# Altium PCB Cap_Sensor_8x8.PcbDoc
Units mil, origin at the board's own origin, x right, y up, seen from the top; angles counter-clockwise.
Board outline 3170 x 4550 mil, 2 copper layers (Top Layer, Bottom Layer); 74 components, 83 nets, 392 pads, 146 vias.
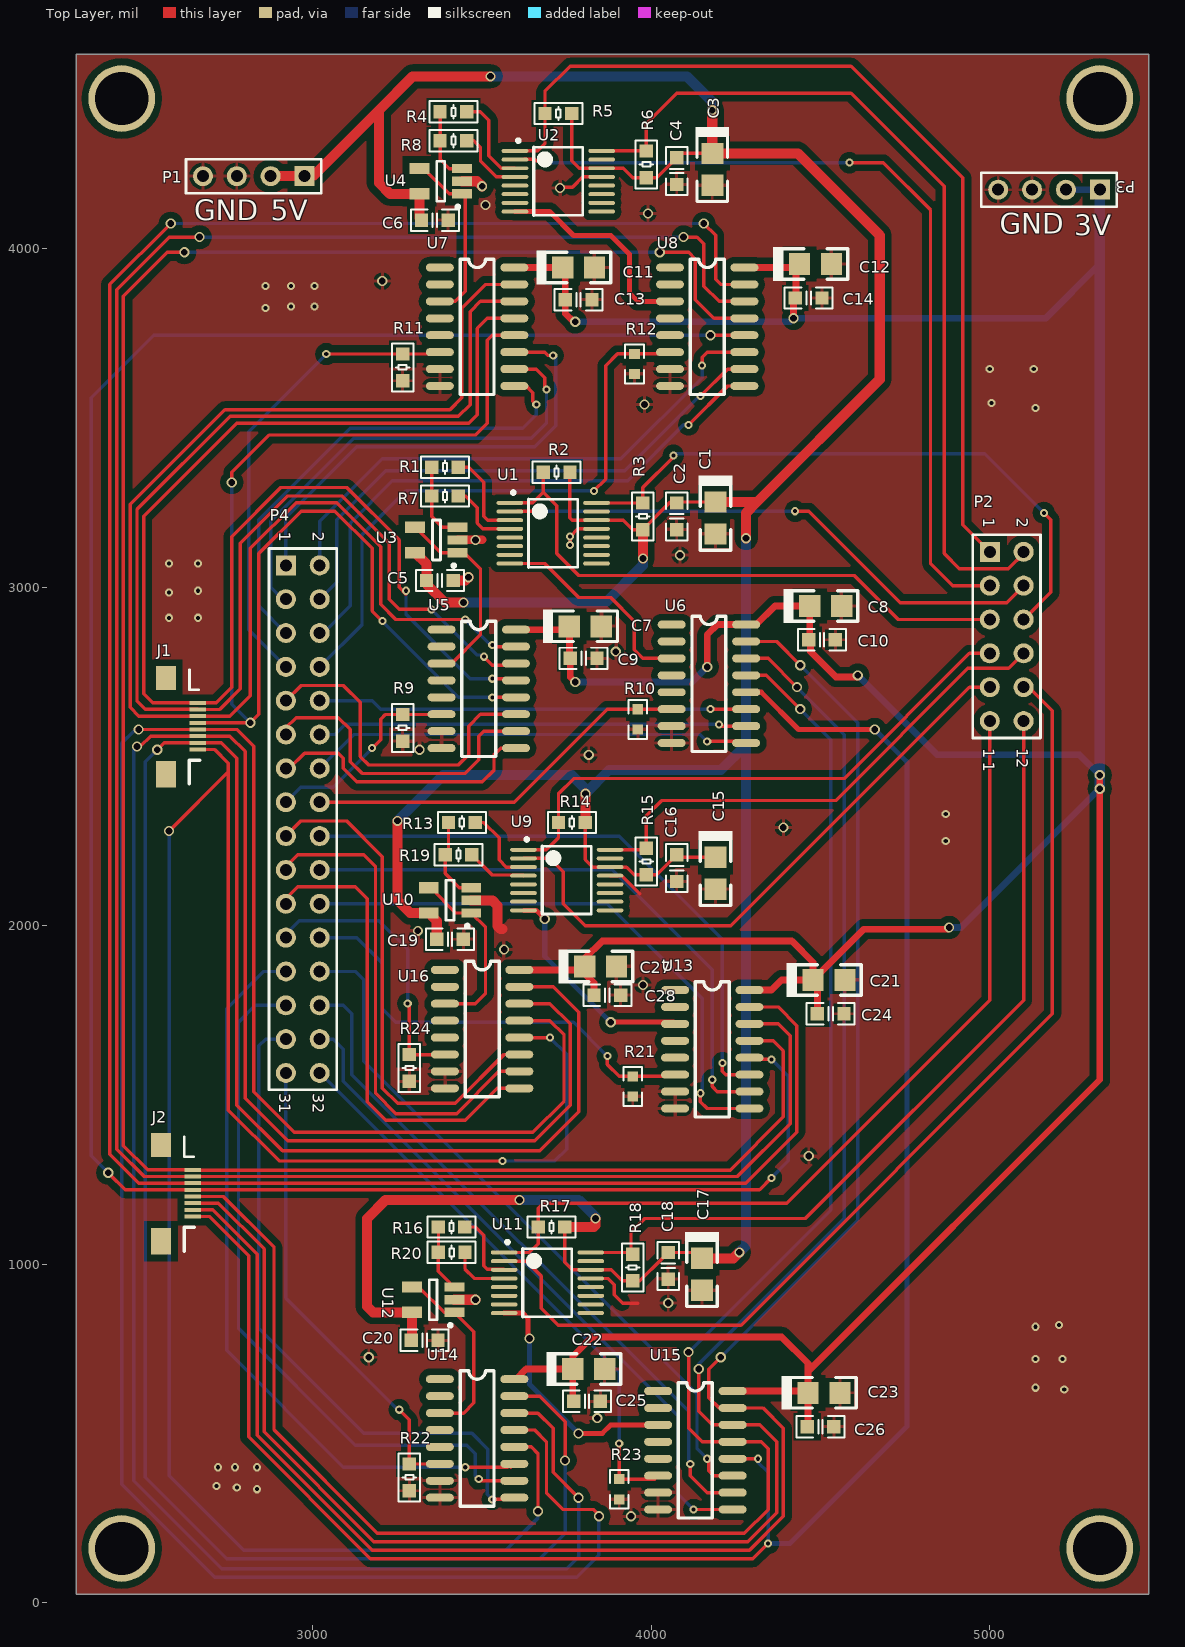
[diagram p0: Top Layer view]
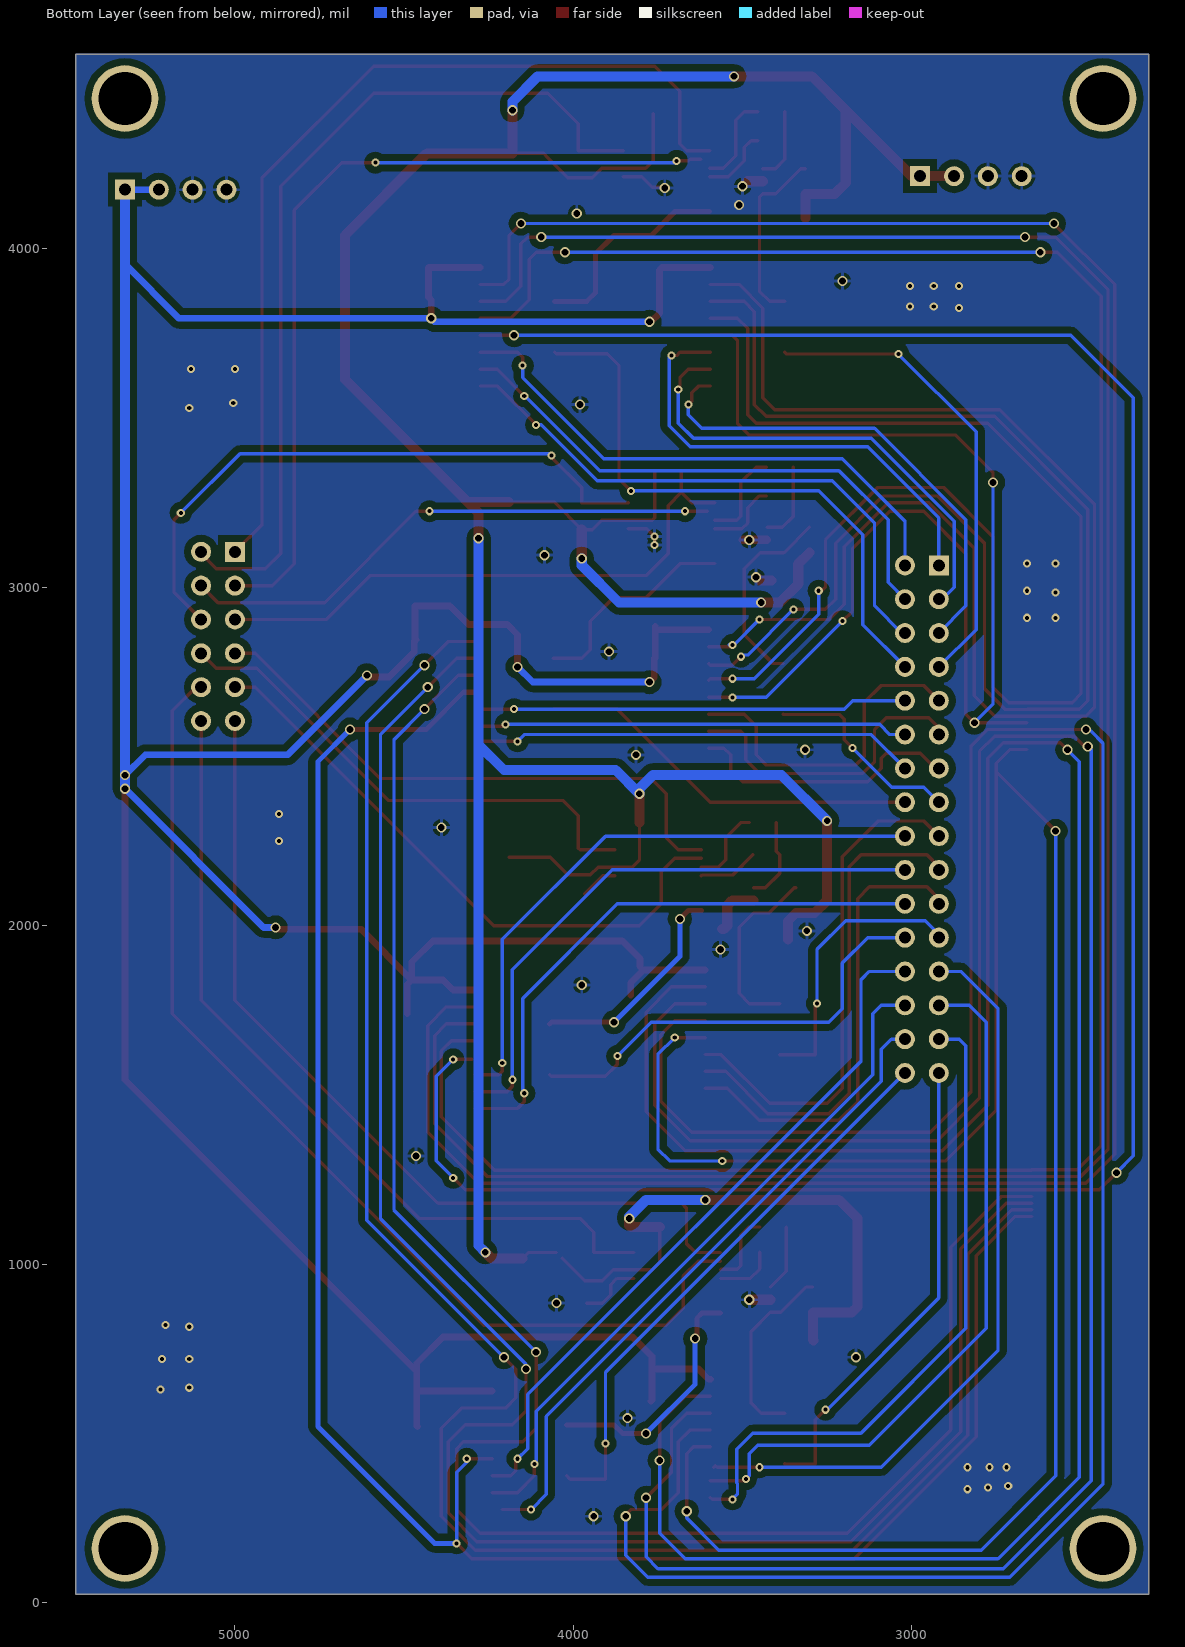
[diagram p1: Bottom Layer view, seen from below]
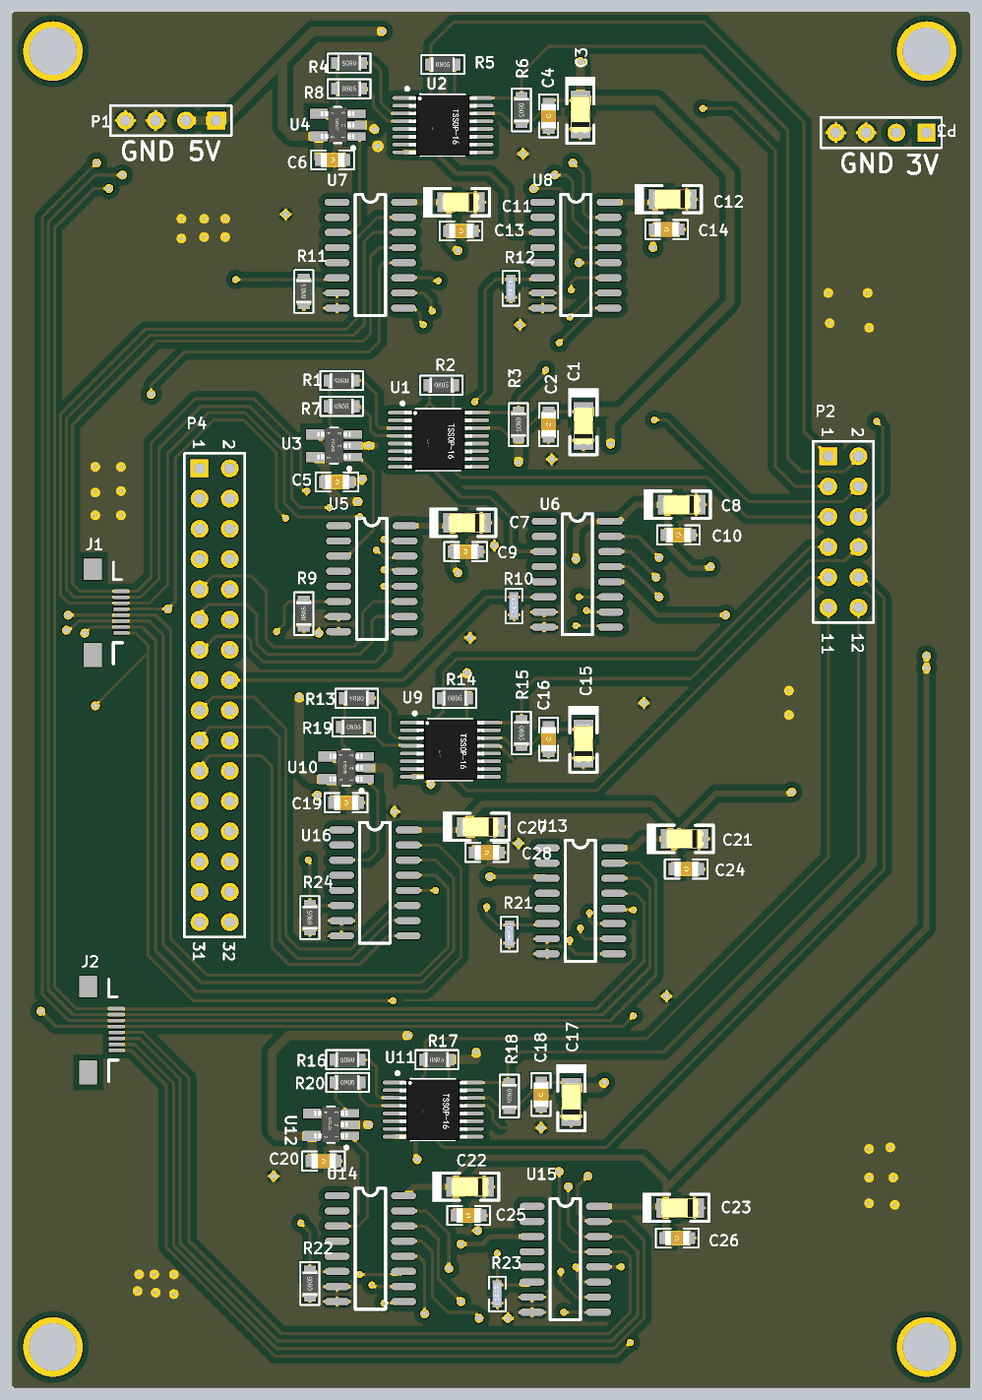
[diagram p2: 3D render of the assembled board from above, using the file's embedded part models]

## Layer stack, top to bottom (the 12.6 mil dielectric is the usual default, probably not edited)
Top Solder: solder mask 0.4, Solder Resist, Dk 3.5
Top Layer: signal copper 1.4
Dielectric 1: dielectric 12.6, FR-4, Dk 4.8
Bottom Layer: signal copper 1.4
Bottom Solder: solder mask 0.4, Solder Resist, Dk 3.5

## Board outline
2300,25 2300,4575 5470,4575 5470,25

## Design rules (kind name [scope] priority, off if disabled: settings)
Clearance Clearance_1 [InPolygon] p1: gap=20 ignorepadtopadclearanceinfootprint=FALSE except(0: Arc-Hole Track-Hole SMDPad-Hole THPad-Hole Via-Hole Fill-Hole Poly-Hole Region-Hole Text-Hole)
Clearance [All] p2: gap=4 ignorepadtopadclearanceinfootprint=FALSE except(0: Arc-Hole Track-Hole SMDPad-Hole THPad-Hole Via-Hole Fill-Hole Poly-Hole Region-Hole Text-Hole)
PolygonConnect [All] p1: connectstyle=Relief reliefconductorwidth=10 reliefentries=4 polygonreliefangle="90 Angle" airgapwidth=10
RoutingVias [All] p1: holewidth=20 width=30 viastyle="Through Hole" minholewidth=20 minwidth=30 maxholewidth=20 maxwidth=30
SolderMaskExpansion [All] p1: expansion=4
Width Width_1 [All] p1: maxlimit=30 minlimit=10 preferedwidth=20
Width Width_vcc [InNet('VDD_5V')] p2: maxlimit=50 minlimit=10 preferedwidth=20
30 further rules are at their usual default settings.

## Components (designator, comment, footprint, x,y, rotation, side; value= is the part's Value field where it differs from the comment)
C1 "Cap Pol2" Cap-TA 4190,3205 r90 top
C2 "Cap" 0805C 4075,3210 r90 top
C3 "Cap Pol2" Cap-TA 4180,4235 r90 top
C4 "Cap" 0805C 4075,4230 r90 top
C5 "Cap" 0805C 3375,3020 r180 top
C6 "Cap" 0805C 3360,4085 r180 top
C7 "Cap Pol2" Cap-TA 3805,2885 r180 top
C8 "Cap Pol2" Cap-TA 4515,2945 r180 top
C9 "Cap" 0805C 3800,2790 r180 top
C10 "Cap" 0805C 4504.37,2845 r180 top
C11 "Cap Pol2" Cap-TA 3785,3945 r180 top
C12 "Cap Pol2" Cap-TA 4485,3955 r180 top
C13 "Cap" 0805C 3785,3850 r180 top
C14 "Cap" 0805C 4465,3855 r180 top
C15 "Cap Pol2" Cap-TA 4190,2155 r90 top
C16 "Cap" 0805C 4075,2170 r90 top
C17 "Cap Pol2" Cap-TA 4150,970 r90 top
C18 "Cap" 0805C 4050,995 r90 top
C19 "Cap" 0805C 3405,1960 r180 top
C20 "Cap" 0805C 3330,775 r180 top
C21 "Cap Pol2" Cap-TA 4525,1840 r180 top
C22 "Cap Pol2" Cap-TA 3815,690 r180 top
C23 "Cap Pol2" Cap-TA 4510,620 r180 top
C24 "Cap" 0805C 4530,1740 r180 top
C25 "Cap" 0805C 3810,595 r180 top
C26 "Cap" 0805C 4500,520 r180 top
C27 "Cap Pol2" Cap-TA 3850,1880 r180 top
C28 "Cap" 0805C 3870,1795 r180 top
J1 "FPC_8P" FPC8-0.5 2660,2658.74 r270 top
J2 "FPC_8P" FPC8-0.5 2645,1278.74 r270 top
P1 "Header 4" HDR1X4 2975,4215 r180 top
P2 "Header 6X2" HDR2X6 5000,3105 r270 top
P3 "Header 4" HDR1X4 5325,4175 r180 top
P4 "Header 16X2" HDR2X16 2920,3065 r270 top
R1 "Res" 0805R 3390,3355 r180 top
R2 "Res" 0805R 3720,3340 r0 top
R3 "Res" 0805R 3975,3210 r270 top
R4 "Res" 0805R 3415,4405 r180 top
R5 "Res" 0805R 3725,4400 r0 top
R6 "Res" 0805R 3985,4250 r270 top
R7 "Res" 0805R 3390,3270 r0 top
R8 "Res" 0805R 3415,4320 r0 top
R9 "Res" 0805R 3265,2585 r90 top
R10 "Res" 0603R 3960,2610 r90 top
R11 "Res" 0805R 3265,3650 r90 top
R12 "Res" 0603R 3950,3660 r90 top
R13 "Res" 0805R 3440,2305 r180 top
R14 "Res" 0805R 3765,2305 r0 top
R15 "Res" 0805R 3985,2190 r270 top
R16 "Res" 0805R 3409.37,1110 r180 top
R17 "Res" 0805R 3705,1110 r0 top
R18 "Res" 0805R 3945,990 r270 top
R19 "Res" 0805R 3430,2210 r0 top
R20 "Res" 0805R 3410,1035 r0 top
R21 "Res" 0603R 3945,1525 r90 top
R22 "Res" 0805R 3285,370 r90 top
R23 "Res" 0603R 3905,335 r90 top
R24 "Res" 0805R 3285,1580 r90 top
U1 "AD7746" TSSOP16 3710,3160 r0 top
U2 "AD7746" TSSOP16 3725,4200 r0 top
U3 "AD8515" sot23-5 3365,3140 r180 top
U4 "AD8515" sot23-5 3377.2,4200 r180 top
U5 "CD4051" SO16 3540,2900 r0 top
U6 "CD4051" SO16 4220,2915 r0 top
U7 "CD4051" SO16 3535,3970 r0 top
U8 "CD4051" SO16 4215,3970 r0 top
U9 "AD7746" TSSOP16 3750,2135 r0 top
U10 "AD8515" sot23-5 3405,2075 r180 top
U11 "AD7746" TSSOP16 3692.95,945 r0 top
U12 "AD8515" sot23-5 3355,895 r180 top
U13 "CD4051" SO16 4230,1835 r0 top
U14 "CD4051" SO16 3535,685 r0 top
U15 "CD4051" SO16 4180,650 r0 top
U16 "CD4051" SO16 3550,1894.57 r0 top

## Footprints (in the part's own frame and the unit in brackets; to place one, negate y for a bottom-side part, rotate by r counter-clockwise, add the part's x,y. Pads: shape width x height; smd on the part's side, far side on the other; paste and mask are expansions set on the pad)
0603R [mm]
  rect 0.76x0.8 smd: 1(-0.76,0) 2(0.76,0)
  silkscreen extent -1.46,-0.7 1.46,0.7, body extent -1,-0.39 1,0.39, height 0.79
0805C [mm]
  rect 1x1 smd: 1(-1,0) 2(1,0)
  silkscreen extent -1.8,-0.8 1.8,0.8, body extent -1.01,-0.62 1,0.63, height 0.92
0805R [mm]
  rect 1x1 smd: 1(-1,0) 2(1,0)
  silkscreen extent -1.8,-0.8 1.8,0.8, body extent -1,-0.63 1,0.63, height 0.55
Cap-TA [mm]
  rect 1.6x1.65 smd: 1(1.2,0) 2(-1.2,0)
  silkscreen extent -2.41,-1.27 3.17,1.27, body extent -1.6,-0.8 1.6,0.8, height 1.61
FPC8-0.5 [mm]
  rect 0.3x1.25 smd: 1(0,0) 2(0.5,0) 3(1,0) 4(1.5,0) 5(2,0) 6(2.5,0) 7(3,0) 8(3.5,0)
  rect 1.8x1.5 smd: 9(-1.85,-2.375)
  rect 2x1.5 smd: 10(5.35,-2.375)
  silkscreen extent -2.48,-0.64 6.1,0.13
HDR1X4 [mm] "Connector; Header; 4 Position"
  rect 1.5x1.5 hole 0.9: 1(0,0)
  round 1.5 hole 0.9: 2(2.54,0) 3(5.08,0) 4(7.62,0)
  silkscreen extent -1.27,-1.27 8.89,1.27
HDR2X6 [mm] "Connector; Header; 6x2 Position"
  rect 1.5x1.5 hole 0.9: 1(0,0)
  round 1.5 hole 0.9: 2(0,2.54) 3(2.54,0) 4(2.54,2.54) 5(5.08,0) 6(5.08,2.54) 7(7.62,0) 8(7.62,2.54) 9(10.16,0) 10(10.16,2.54) 11(12.7,0) 12(12.7,2.54)
  silkscreen extent -1.27,-1.27 13.97,3.81
HDR2X16 [mm] "Connector; Header; 16x2 Position"
  rect 1.5x1.5 hole 0.9: 1(0,0)
  round 1.5 hole 0.9: 2(0,2.54) 3(2.54,0) 4(2.54,2.54) 5(5.08,0) 6(5.08,2.54) 7(7.62,0) 8(7.62,2.54) 9(10.16,0) 10(10.16,2.54) 11(12.7,0) 12(12.7,2.54) 13(15.24,0) 14(15.24,2.54) 15(17.78,0) 16(17.78,2.54) 17(20.32,0) 18(20.32,2.54) 19(22.86,0) 20(22.86,2.54) 21(25.4,0) 22(25.4,2.54) 23(27.94,0) 24(27.94,2.54) 25(30.48,0) 26(30.48,2.54) 27(33.02,0) 28(33.02,2.54) 29(35.56,0) 30(35.56,2.54) 31(38.1,0) 32(38.1,2.54)
  silkscreen extent -1.27,-1.27 39.37,3.81
SO16 [mm]
  oval 2.1x0.6 smd: 1(-4.064,-0.635) 2(-4.064,-1.905) 3(-4.064,-3.175) 4(-4.064,-4.445) 5(-4.064,-5.715) 6(-4.064,-6.985) 7(-4.064,-8.255) 8(-4.064,-9.525) 9(1.524,-9.525) 10(1.524,-8.255) 11(1.524,-6.985) 12(1.524,-5.715) 13(1.524,-4.445) 14(1.524,-3.175) 15(1.524,-1.905) 16(1.524,-0.635)
  silkscreen extent -2.54,-10.16 0,0
sot23-5 [mm]
  rect 1.5x0.7 smd: 1(-1.595,0.95) 2(-1.595,0) 3(-1.595,-0.95)
  rect 1.5x0.85 smd: 4(1.595,-0.95) 5(1.595,0.95)
  silkscreen extent -1.42,-1.5 0.3,2.05, body extent -1.39,-1.46 1.41,1.44, height 1.09
TSSOP16 [mm]
  oval 2x0.3 smd: 1(-3.25,2.275) 2(-3.25,1.625) 3(-3.25,0.975) 4(-3.25,0.325) 5(-3.25,-0.325) 6(-3.25,-0.975) 7(-3.25,-1.625) 8(-3.25,-2.275) 9(3.25,-2.275) 10(3.25,-1.625) 11(3.25,-0.975) 12(3.25,-0.325) 13(3.25,0.325) 14(3.25,0.975) 15(3.25,1.625) 16(3.25,2.275)
  silkscreen extent -3.12,-2.55 1.83,3.17, body extent -2.85,-2.56 2.85,2.54, height 1.45

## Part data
C1 C3 C7 C8 C11 C12 C15 C17 C21 C22 C23 C27: "Polarized Capacitor (Axial)"
C2 C4 C5 C6 C9 C10 C13 C14 C16 C18 C19 C20 C24 C25 C26 C28: "Capacitor"
P1 P3: "Header, 4-Pin"
P2: "Header, 6-Pin, Dual row"
P4: "Header, 16-Pin, Dual row"
R1 R2 R3 R4 R5 R6 R7 R8 R9 R10 R11 R12 R13 R14 R15 R16 R17 R18 R19 R20 R21 R22 R23 R24: "Resistor"

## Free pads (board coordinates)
  round 196.85 hole 157.48: 0(2435,4444.37) 1(5325,4444.37) 2(5325,160) 3(2435,160)

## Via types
v1: diameter 24, hole 12, Top Layer to Bottom Layer, 77 vias
v2: diameter 30, hole 20, Top Layer to Bottom Layer, 69 vias

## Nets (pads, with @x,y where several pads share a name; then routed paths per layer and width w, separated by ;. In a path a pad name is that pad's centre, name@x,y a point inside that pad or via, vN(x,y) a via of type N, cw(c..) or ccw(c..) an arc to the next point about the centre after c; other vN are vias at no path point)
GND: C1.2 C2.1 C3.2 C4.1 C5.1 C6.1 C7.2 C8.2 C9.1 C10.1 C11.2 C12.2 C13.1 C14.1 C15.2 C16.1 C17.2 C18.1 C19.1 C20.1 C21.2 C22.2 C23.2 C24.1 C25.1 C26.1 C27.2 C28.1 P1.3 P1.4 P3.3 P3.4 R9.1 R10.1 R11.1 R12.1 R21.1 R22.1 R23.1 R24.1 U1.13 U2.13 U3.2 U4.2 U5.7 U5.8 U6.7 U6.8 U7.7 U7.8 U8.7 U8.8 U9.13 U10.2 U11.13 U12.2 U13.7 U13.8 U14.7 U14.8 U15.7 U15.8 U16.7 U16.8 | length 957.9
  Top Layer w10: v2(3730,4180) 3731.98,4181.98 3766.98,4181.98 3797.8,4212.8 U2.13 ; v1(3760,3125) v1(3760,3150) 3782.8,3172.8 U1.13 ; U11.13 3871.16,957.8 3889.99,938.97 3889.99,910.01 3915,885 3960,885 ; U9.13 3912.96,2147.8 3965.76,2095
  Top Layer w25: U3.2 v2(3480,3140) 3500,3140
  Top Layer w30: C5.1 3450,3020 v2(3460,3030) ; U12.2 v2(3480,895) ; U4.2 3485,4200 v2(3500,4185) ; U10.2 3530,2075 3545,2060 3545,1999.7 3554.7,1990 3560,1990
  other v1: 2835,335 2775,340 2715,345 2720,400 2770,400 2835,400 5220,630 5135,635 5135,720 5215,720 5135,815 5205,820 4870,2250 4870,2330 2575,2910 2660,2910 2575,2985 2660,2990 2575,3070 2660,3070 5135,3530 5005,3545 5000,3645 5130,3645 2860,3825 2935,3830 3005,3830 2860,3890 2935,3890 3005,3890
  other v2: 3940,255 3840,545 3165,725 4050,885 4465,1320 3975,1825 3565,1930 3310,1985 4390,2290 3815,2505 3315,2520 3895,2810 4085,3095 3980,3540 3205,3905 3990,4105 3510,4130
NetR1_1: R1.1 U1.3 | length 276.1
  Top Layer w10: R1.1 3460,3355 3505,3310 3505,3210 3516.61,3198.39 U1.3
NetR1_2: R1.2 R7.1 U3.3 | length 236
  Top Layer w10: R1.2 R7.1 3350.63,3209.37 3382.6,3177.4 U3.3
NetR4_1: R4.1 U2.3 | length 273.2
  Top Layer w10: R4.1 3495,4405 3520,4380 3520,4275 3556.61,4238.39 U2.3
NetR4_2: R4.2 R8.1 U4.3 | length 216.2
  Top Layer w10: R4.2 R8.1 3375.63,4264.37 3402.6,4237.4 U4.3
NetR7_2: R7.2 U1.4 | length 219.3
  Top Layer w10: R7.2 3450,3270 3485,3235 3485,3190 3502.2,3172.8 U1.4
NetR8_2: R8.2 U2.4 | length 210.5
  Top Layer w10: R8.2 3475,4320 3495,4300 3495,4260 3542.2,4212.8 U2.4
NetR13_1: R13.1 U9.3 | length 235.3
  Top Layer w10: R13.1 3505,2305 3550,2260 3550,2195 3571.61,2173.39 U9.3
NetR13_2: R13.2 R19.1 U10.3 | length 249.3
  Top Layer w10: R13.2 3400.63,2220 R19.1 3390.63,2154.37 3432.6,2112.4 U10.3
NetR16_1: R16.1 U11.3 | length 221.4
  Top Layer w10: R16.1 3480,1110 3505,1085 3505,995 3515,985 3563.39,985 U11.3
NetR16_2: R16.2 R20.1 U12.3 | length 198.3
  Top Layer w10: R16.2 3371,1110 3371,1035.37 R20.1 3370.63,979.57 U12.3
NetR19_2: R19.2 U9.4 | length 178.4
  Top Layer w10: R19.2 3529.37,2150 3619.84,2150 U9.4
NetR20_2: R20.2 U11.4 | length 176.5
  Top Layer w10: R20.2 3449.37,985.63 3477.2,957.8 U11.4
RDY1: P2.3 U2.2 | length 2510.4
  Top Layer w10: U2.2@3623.66,4265 3655,4265 3660,4260 v1(3695,4260) ; v1(4585,4255) 4685,4255 4825,4115 4825,3070 4890,3005 P2.3
  Bottom Layer w10: v1(3695,4260) 3700,4255 v1(4585,4255)
RDY2: P2.4 U1.2 | length 1628.9
  Top Layer w10: U1.2@3603.66,3225 v1(3670,3225) ; v1(4425,3225) 4465,3225 4735,2955 5050,2955 P2.4
  Bottom Layer w10: v1(3670,3225) v1(4425,3225)
RDY3: P2.9 U9.2 | length 1808
  Top Layer w10: U9.2 3701.02,2198.98 3740,2160 3740,2065 3805,2000 4235,2000 4940,2705 P2.9
RDY4: P2.10 U11.2 | length 3144
  Top Layer w10: U11.2 3631.02,1008.98 3675,965 3675,870 3725,820 4265,820 5185,1740 5185,2635 5115,2705 P2.10
SCL1: P2.1 R5.1 U2.1 | length 2792.3
  Top Layer w10: U2.1 3664.57,4289.57 3685.63,4310.63 R5.1 3685.63,4465.63 3760,4540 4590,4540 4920,4210 4920,3185 P2.1
SCL2: P2.5 R2.1 U1.1 | length 1728.5
  Top Layer w10: U1.1 3649.57,3249.57 3680.63,3280.63 ; R2.1 3680.63,3280.63 ; P2.5 4730,2905 4600,3035 3785,3035 3720,3100 3720,3241.26 3680.63,3280.63
SCL3: P2.7 R14.1 U9.1 | length 1694.5
  Top Layer w10: U9.1 3689.57,2224.57 3725.63,2260.63 R14.1 3725.63,2390.63 3770,2435 4570,2435 4940,2805 P2.7
SCL4: P2.11 R17.1 U11.1 | length 2630.3
  Top Layer w10: U11.1 3639.57,1034.57 3665.63,1060.63 R17.1 3665.63,1165.63 3680,1180 4400,1180 5000,1780 P2.11
SDA1: P2.2 R6.1 U2.16 | length 2606.2
  Top Layer w10: U2.16 3984.8,4289.57 R6.1 3985,4370 4075,4460 4590,4460 4865,4185 4865,3100 4910,3055 5055,3055 5100,3100 P2.2
SDA2: P2.6 R3.1 U1.16 | length 1828.9
  Top Layer w10: U1.16 3838.15,3249.37 R3.1 3975,3295 v1@4065,3385 ; P2.6 5180,2985 5180,3200 v1(5160,3220)
  Bottom Layer w10: v1@4070,3395 4985,3395 v1(5160,3220)
  other v1: 4065,3390
SDA3: P2.8 R15.1 U9.16 | length 1518.5
  Top Layer w10: U9.16 3980.2,2224.57 R15.1 3985,2325 4030,2370 4545,2370 4935.47,2760.47 5055.47,2760.47 P2.8
SDA4: P2.12 R18.1 U11.16 | length 2448.1
  Top Layer w10: U11.16 3939.8,1034.57 3939.8,1094.8 3980,1135 4455,1135 5100,1780 P2.12
Switch1_Down: U2.8 U8.3 | length 635.3
  Top Layer w15: U2.8 3699.57,4110.43 3770,4040 3880,4040 3935,3985 3935,3870 3960,3845 U8.3
Switch1_Down_A: P4.2 U8.11 | length 1627.3
  Top Layer w10: v1(4150,3655) 4150,3680 4165,3695 U8.11
  Bottom Layer w10: P4.2 3020,3195 3205,3380 3910,3380 4150,3620 v1(4150,3655)
Switch1_Down_B: P4.4 U8.10 | length 1645
  Top Layer w10: v1(4145,3565) 4225,3645 U8.10
  Bottom Layer w10: P4.4 3070,3015 3070,3200 3215,3345 3921.82,3345 4141.82,3565 v1(4145,3565)
Switch1_Down_C: P4.6 U8.9 | length 1700.9
  Top Layer w10: v1(4110,3480) 4225,3595 U8.9
  Bottom Layer w10: P4.6 3030,2865 3110,2945 3110,3190 3235,3315 3930,3315 4095,3480 v1(4110,3480)
Switch1_Down_INH: P4.8 R12.2 U8.6 | length 1771.7
  Top Layer w10: v1(3830,3285) 3865,3320 3865,3655 3899.92,3689.92 R12.2 4049.92,3689.92 U8.6
  Bottom Layer w10: P4.8 3145,2890 3145,3155 3275,3285 v1(3830,3285)
Switch1_Up: U4.1 U4.4 U7.3 | length 535.7
  Top Layer w10: U4.4 3327.6,4237.4 3402.4,4162.6 U4.1 3450,4152.6 3450,3875 3420,3845 U7.3
Switch1_Up_A: P4.1 U7.11 | length 1379.7
  Top Layer w10: U7.11 3685,3695 3695,3685 v1(3710,3685)
  Bottom Layer w10: P4.1 2920,3205 3130,3415 3655,3415 3717,3477 3717,3678 v1(3710,3685)
Switch1_Up_B: P4.3 U7.10 | length 1427
  Top Layer w10: U7.10 3660,3645 3685,3620 3685,3590 v1(3690,3585)
  Bottom Layer w10: P4.3 2910,2965 2875,3000 2875,3195 3120,3440 3645,3440 3690,3485 v1(3690,3585)
Switch1_Up_C: P4.5 U7.9 | length 1449
  Top Layer w10: U7.9 3630,3595 3650,3575 3650,3550 v1(3660,3540)
  Bottom Layer w10: P4.5 2840,2945 2840,3200 3110,3470 3620,3470 3660,3510 v1(3660,3540)
Switch1_Up_INH: P4.7 R11.2 U7.6 | length 1402.9
  Top Layer w10: v1(3039.37,3689.37) R11.2 3369.37,3689.37 U7.6
  Bottom Layer w10: P4.7 2810,2875 2810,3460 v1(3039.37,3689.37)
Switch2_Down: U1.8 U6.3 | length 643.9
  Top Layer w10: U1.8 3684.57,3070.43 3785,2970 3880,2970 3950,2900 3950,2815 3975,2790 U6.3
Switch2_Down_A: P4.10 U6.11 | length 1270.4
  Top Layer w10: v1(4175,2640) U6.11
  Bottom Layer w10: P4.10 3175,2665 3200,2640 v1(4175,2640)
Switch2_Down_B: P4.12 U6.10 | length 1274.5
  Top Layer w10: v1(4200,2595) 4205,2590 U6.10
  Bottom Layer w10: P4.12 3065,2565 3095,2595 v1(4200,2595)
Switch2_Down_C: P4.14 U6.9 | length 1311.8
  Top Layer w10: v1(4165,2545) 4275,2545 U6.9
  Bottom Layer w10: P4.14 3120,2565 4145,2565 v1(4165,2545)
Switch2_Down_INH: P4.16 R10.2 U6.6 | length 1153.9
  Top Layer w10: P4.16 3595,2365 3869.92,2639.92 R10.2 4059.92,2639.92 U6.6
Switch2_Up: U3.1 U3.4 U5.3 | length 588.7
  Top Layer w10: U3.4 3302.6,3177.4 3377.4,3102.6 U3.1 3447.4,3102.6 3495,3055 3495,2860 3410,2775 U5.3
Switch2_Up_A: P4.9 U5.11 | length 1001.6
  Top Layer w10: P4.9 2965,2710 3090,2710 3140,2660 3140,2500 3165,2475 3430,2475 3460,2505 3460,2590 3495,2625 U5.11
Switch2_Up_B: P4.11 U5.10 | length 929.2
  Top Layer w10: P4.11 2920,2585 2950,2615 3075,2615 3110,2580 3110,2485 3145,2450 3450,2450 3490,2490 3490,2560 3505,2575 U5.10
Switch2_Up_C: P4.13 U5.9 | length 819.2
  Top Layer w10: P4.13 2930,2465 2975,2510 3075,2510 3090,2495 3090,2465 3130,2425 3500,2425 3535,2460 3535,2505 3555,2525 U5.9
Switch2_Up_INH: P4.15 R9.2 U5.6 | length 602.8
  Top Layer w10: v1(3175,2525) 3200,2550 3200,2610 3214.37,2624.37 R9.2 3379.37,2624.37 U5.6
  Bottom Layer w10: P4.15 2964.53,2409.53 3059.53,2409.53 v1(3175,2525)
Switch3_Down: U9.8 U13.3 | length 651.3
  Top Layer w15: U9.8 3659.57,2045.43 v2(3685,2020) ; v2(3880,1715) 4065,1715 U13.3
  Bottom Layer w15: v2(3685,2020) 3685,1910 v2(3880,1715)
Switch3_Down_A: P4.18 U13.11 | length 1790.5
  Top Layer w10: v1(4210,1595) 4210,1570 4220,1560 U13.11
  Bottom Layer w10: P4.18 3905,2265 4210,1960 v1(4210,1595)
Switch3_Down_B: P4.20 U13.10 | length 1743.4
  Top Layer w10: v1(4180,1545) 4180,1525 4195,1510 U13.10
  Bottom Layer w10: P4.20 3885,2165 4180,1870 v1(4180,1545)
Switch3_Down_C: P4.22 U13.9 | length 1706.3
  Top Layer w10: v1(4145,1505) 4145,1480 4165,1460 U13.9
  Bottom Layer w10: P4.22 3870,2065 4150,1785 4150,1510 v1(4145,1505)
Switch3_Down_INH: P4.24 R21.2 U13.6 | length 1315.7
  Top Layer w10: v1(3870,1615) 3870,1590 3905.08,1554.92 R21.2 4064.92,1554.92 U13.6
  Bottom Layer w10: P4.24 3130,1965 3205,1890 3205,1755 3245,1715 3770,1715 v1(3870,1615)
Switch3_Up: U10.1 U10.4 U16.3 | length 544.3
  Top Layer w10: U10.4 3347.6,2112.4 3422.4,2037.6 U10.1 3510,1995.39 3510,1800 3479.57,1769.57 U16.3
Switch3_Up_A: P4.17 U16.11 | length 1514.7
  Top Layer w10: P4.17 2964.53,2309.53 3099.53,2309.53 3205,2204.06 3205,1520 3250,1475 3420,1475 3564.57,1619.57 U16.11
Switch3_Up_B: P4.19 U16.10 | length 1475.4
  Top Layer w10: P4.19 2920,2175 2955,2210 3150,2210 3185,2175 3185,1505 3245,1445 3425,1445 3549.57,1569.57 U16.10
Switch3_Up_C: P4.21 U16.9 | length 1395.9
  Top Layer w10: P4.21 2920,2080 2955,2115 3125,2115 3160,2080 3160,1480 3215,1425 3450,1425 3544.57,1519.57 U16.9
Switch3_Up_INH: P4.23 R24.2 U16.6 | length 839.3
  Top Layer w10: v1(3280,1770) 3285,1765 R24.2 U16.6@3389.8,1619.37
  Bottom Layer w10: P4.23 2920,1975 2960,2015 3195,2015 3280,1930 v1(3280,1770)
Switch4_Down: U11.8 U15.3 | length 723.9
  Top Layer w15: U11.8 3619.57,855.43 3635,840 3635,785 v2(3640,780) ; v2(3785,500) 3855,500 3880,525 U15.3
  Bottom Layer w15: v2(3640,780) 3640,645 v2(3785,500)
Switch4_Down_A: P4.26 U15.11 | length 2089.1
  Top Layer w10: v1(4165,425) 4170,420 4170,390 4185,375 U15.11
  Bottom Layer w10: P4.26 3125,1865 3150,1840 3150,1600 4135,615 4135,455 v1(4165,425)
Switch4_Down_B: P4.28 U15.10 | length 2030.3
  Top Layer w10: v1(4115,410) 4115,375 4165,325 U15.10
  Bottom Layer w10: P4.28 3090,1765 3115,1740 3115,1560 4110,565 4110,415 v1(4115,410)
Switch4_Down_C: P4.30 U15.9 | length 1956.1
  Top Layer w10: v1(4125,275) U15.9@4210,275
  Bottom Layer w10: P4.30 3060,1665 3090,1635 3090,1540 4080,550 4080,320 v1(4125,275)
Switch4_Down_INH: P4.32 R23.2 U15.6 | length 1685.8
  Top Layer w10: v1(3905,470) R23.2 4009.92,364.92 U15.6
  Bottom Layer w10: P4.32 3905,680 v1(3905,470)
Switch4_Up: U12.1 U12.4 U14.3 | length 560.3
  Top Layer w10: U12.4 3312.6,932.4 3387.4,857.6 U12.1 3475,800.39 3475,590 3445,560 U14.3
Switch4_Up_A: P4.25 U14.11 | length 2217.6
  Top Layer w10: v1(3450,400) 3575,400 3580,405 U14.11@3585,400
  Bottom Layer w10: P4.25 2855,1865 2745,1755 2745,745 3090,400 v1(3450,400)
Switch4_Up_B: P4.27 U14.10 | length 2105.2
  Top Layer w10: v1(3490,365) 3495,360 U14.10
  Bottom Layer w10: P4.27 2830,1765 2780,1715 2780,810 3125,465 3455,465 3480,440 3480,375 v1(3490,365)
Switch4_Up_C: P4.29 U14.9 | length 1970.3
  Top Layer w10: v1(3530,305) 3590,305 U14.9
  Bottom Layer w10: P4.29 2860,1665 2840,1645 2840,810 3150,500 3470,500 3517,453 3517,353.82 3515,351.82 3515,320 v1(3530,305)
Switch4_Up_INH: P4.31 R22.2 U14.6 | length 1400
  Top Layer w10: v1(3255,570) 3285,540 R22.2 3374.37,409.37 U14.6
  Bottom Layer w10: P4.31 2920,900 3250,570 v1(3255,570)
Switch_Down_CH0: J2.1 U8.13 U13.13 | length 6902.2
  Top Layer w10: v2(2620,3990) 2570,3990 2440,3860 2440,1350 2511.26,1278.74 J2.1 2645.74,1278 4233,1278 4390,1435 4390,1630 4360,1660 U13.13 ; v2(4025,3990) 4110,3990 4130,3970 4130,3850 4185,3795 U8.13
  Bottom Layer w10: v2(2620,3990) v2(4025,3990)
Switch_Down_CH1: J2.2 U8.14 U13.14 | length 7093.7
  Top Layer w10: v2(2665,4035) 2575,4035 2420,3880 2420,1340 2500.95,1259.05 J2.2 4254.05,1259.05 4410,1415 4410,1675 4375,1710 U13.14 ; v2(4095,4035) 4135,4035 4155,4015 4155,3890 4200,3845 U8.14
  Bottom Layer w10: v2(2665,4035) v2(4095,4035)
Switch_Down_CH2: J2.3 U8.15 U13.15 | length 7275.9
  Top Layer w10: v2(2580,4075) 2400,3895 2400,1325 2485.63,1239.37 J2.3 4279.37,1239.37 4430,1390 4430,1705 4375,1760 U13.15 ; v2(4155,4075) 4190,4040 4190,3910 4205,3895 U8.15
  Bottom Layer w10: v2(2580,4075) v2(4155,4075)
Switch_Down_CH3: J2.4 U8.12 U13.12 | length 6752.2
  Top Layer w10: v2@2400,1265 2445.32,1219.68 J2.4 4319.68,1219.68 v1(4355,1255) ; v2(4175,3745) U8.12 ; U13.12@4300,1605 v1(4355,1605)
  Bottom Layer w10: v2(2395,1270) 2345,1320 2345,3560 2530,3745 v2(4175,3745) ; v1(4355,1255) 4405,1305 4405,1555 v1(4355,1605)
Switch_Down_CH4: J2.5 U6.13 U15.13 | length 5435
  Top Layer w10: J2.5 2735,1200 2885,1050 2885,510 3190,205 4275,205 4345,275 4345,455 4325,475 U15.13 4150,475 4110,515 v2(4110,740) ; U6.13 4340,2740 v2(4440,2640)
  Bottom Layer w10: v2(4110,740) 4530,1160 4530,2550 v2(4440,2640)
Switch_Down_CH5: J2.6 U6.14 U15.14 | length 5529.8
  Top Layer w10: J2.6 2720.31,1180.31 2855.63,1045 2855.63,504.37 3180,180 4285,180 4370,265 4370,475 4320,525 U15.14 4180,525 4140,565 v2(4140,690) ; U6.14 4345,2790 v2(4430,2705)
  Bottom Layer w10: v2(4140,690) 4140,705 4570,1135 4570,2565 v2(4430,2705)
Switch_Down_CH6: J2.7 U6.15 U15.15 | length 5640.3
  Top Layer w10: J2.7 2704.37,1160.63 2835,1030 2835,495 3175,155 4290,155 4390,255 4390,515 4330,575 U15.15 4200,575 4170,605 4170,690 v2(4205,725) ; U6.15 4370,2840 v2(4440,2770)
  Bottom Layer w10: v2(4205,725) 4610,1130 4610,2600 v2(4440,2770)
Switch_Down_CH7: J2.8 U6.12 U15.12 | length 5870.2
  Top Layer w10: J2.8 2694.06,1140.94 2810,1025 2810,490 3170,130 4300,130 v1(4345,175) ; U15.12 v1(4315,425)
  Top Layer w15: U6.12 4325,2690 4435,2580 4650,2580 4655,2585 v2(4660,2580)
  Bottom Layer w10: v1(4315,425) 4315,415 4345,385 v1(4345,175)
  Bottom Layer w15: v1(4345,175) 4410,175 4755,520 4755,2485 v2(4660,2580)
Switch_Up_CH0: J1.1 U5.13 U7.13 | length 4020
  Top Layer w10: v1(3275,2990) 3275,2980 3255,3000 3255,3140 3100,3295 2905,3295 2760,3150 2760,2705 2713.74,2658.74 J1.1 2526.26,2658.74 2500,2685 2500,3210 2775,3485 3460,3485 3485,3510 3485,3765 3515,3795 U7.13 ; v1(3530,2730) 3595,2730 U5.13
  Bottom Layer w10: v1(3275,2990) 3275,2920 3465,2730 v1(3530,2730)
Switch_Up_CH1: J1.2 U5.14 U7.14 | length 4044.3
  Top Layer w10: J1.2@2659.05,2640 2505,2640 2480,2665 2480,3230 2755,3505 3430,3505 3465,3540 3465,3815 3495,3845 U7.14 ; J1.2 2724.05,2639.05 2785,2700 2785,3130 2925,3270 3085,3270 3225,3130 3225,2965 3255,2935 v1(3350,2935) ; v1(3505,2795) 3530,2770 3595,2770 U5.14
  Bottom Layer w10: v1(3350,2935) 3485,2800 3500,2800 v1(3505,2795)
Switch_Up_CH2: J1.3 U5.15 U7.15 | length 4110.3
  Top Layer w10: v1(3450,2905) 3245,2905 3200,2950 3200,3120 3070,3250 2950,3250 2815,3115 2815,2680 2754.37,2619.37 J1.3 2485.63,2619.37 2460,2645 2460,3245 2740,3525 3405,3525 3440,3560 3440,3825 3510,3895 U7.15 ; v1(3530,2830) 3535,2825 U5.15
  Bottom Layer w10: v1(3450,2905) v1@3527.5,2827.5 ; v1(3530,2830) v1@3540,2830
Switch_Up_CH3: J1.4 U5.12 U7.12 | length 3722.5
  Top Layer w10: J1.4 2814.68,2599.68 v2(2815,2600) 2840,2625 2840,3100 2965,3225 3065,3225 3175,3115 3175,2930 v1(3205,2900) ; v2(2760,3310) 2760,3340 2870,3450 3480,3450 3515,3485 3515,3730 3530,3745 U7.12 ; v1(3530,2675) U5.12
  Bottom Layer w10: v2(2760,3310) 2760,2655 v2(2815,2600) ; v1(3205,2900) 3430,2675 v1(3530,2675)
Switch_Up_CH4: J1.5 U14.13 U16.13 | length 7092.5
  Top Layer w10: v2@2475,2580 J1.5 2775,2580 2825,2530 2825,1510 2945,1390 3650,1390 3742,1482 3742,1678 3700.43,1719.57 U16.13 ; U14.13 3655,510 3690,475 3690,325 3740,275 3830,275 3845,260 v2(3845,255)
  Bottom Layer w10: 2470,2575 2435,2540 2435,350 2710,75 3780,75 3845,140 v2(3845,255)
  other v2: 2485,2580
Switch_Up_CH5: J1.6 U14.14 U16.14 | length 7005.2
  Top Layer w10: v2(2480,2530) 2490,2530 2520.31,2560.31 J1.6 2754.69,2560.31 2800,2515 2800,1490 2925,1365 3655,1365 3760,1470 3760,1710 3700.43,1769.57 U16.14 ; U14.14 3665,560 3710,515 3710,385 3780,315 3780,310 v2(3785,310)
  Bottom Layer w10: v2(2480,2530) 2470,2520 2470,360 2730,100 3750,100 3785,135 v2(3785,310)
Switch_Up_CH6: J1.7 U14.15 U16.15 | length 6947.9
  Top Layer w10: v2(2540,2520) 2560.63,2540.63 J1.7 2729.37,2540.63 2775,2495 2775,1470 2910,1335 3670,1335 3785,1450 3785,1745 3710.43,1819.57 U16.15 ; U14.15 3670,610 3745,535 v2(3745,420)
  Bottom Layer w10: v2(2540,2520) 2505,2485 2505,370 2745,130 3670,130 3745,205 v2(3745,420)
Switch_Up_CH7: J1.8 U14.12 U16.12 | length 6290.4
  Top Layer w10: v2(2575,2280) 2750,2455 ; J1.8 2709.06,2520.94 2750,2480 2750,2455 ; v1(3560,1305) 2900,1305 2750,1455 2750,2455 ; U14.12 3645,460 3665,440 v2(3665,270) ; U16.12 v1(3700.43,1669.57)
  Bottom Layer w10: v2(2575,2280) 2575,375 2795,155 3570,155 3665,250 v2(3665,270) ; v1(3560,1305) 3715,1305 3750,1340 3750,1620 v1(3700.43,1669.57)
VDD_3V3: C7.1 C8.1 C9.2 C10.2 C11.1 C12.1 C13.2 C14.2 C21.1 C22.1 C23.1 C24.2 C25.2 C26.2 C27.1 C28.2 P3.1 P3.2 U5.16 U6.16 U7.16 U8.16 U13.16 U14.16 U15.16 U16.16 | length 12490.1
  Top Layer w20: U14.16 3600,660 3630,690 C22.1 ; U7.16 C11.1 3745.63,3937.13 C13.2 3745.63,3809.37 3770,3785 v2(3775,3785) ; U5.16 C7.1@3747.76,2875 ; U16.16 3792.32,1869.57 3830.63,1831.26 C28.2 ; C7.1 3757.76,2792.87 C9.2 3760.63,2734.37 v2(3775,2720) ; C25.2 3767.76,597.87 C22.1 ; C27.1 3802.76,1902.76 3855,1955 4415,1955 4477.76,1892.24 C21.1 ; v2(4165,2765) 4165,2860 4195,2890 U6.16 4310,2890 4365,2945 C8.1 4467.76,2847.76 C10.2 4470,2840 4470,2810 4545,2735 4610,2735 v2(4610,2740) ; U15.16 4457.76,625 C23.1 ; U8.16 4427.76,3945 4427.76,3857.13 C14.2 4420,3849.37 v2(4420,3795) ; U13.16 4355,1810 4385,1840 C21.1 ; C26.2 4462.76,522.13 C23.1 ; C24.2 4490.63,1827.13 C21.1 ; v2(4880,1995) 4875,1990 4627.76,1990 C21.1 ; v2(5325,2445) 5325,1545 4462.76,682.76 ; C22.1 3767.76,727.76 3825,785 4385,785 4462.76,707.24 4462.76,682.76 ; C23.1 4462.76,682.76
  Bottom Layer w20: v2(3775,2720) 4120,2720 v2(4165,2765) ; v2(3775,3785) 4410,3785 v2(4420,3795) 5165,3795 5325,3955 ; v2(4610,2740) 4845,2505 5265,2505 v2(5325,2445) ; v2(4880,1995) 4915,1995 v2(5325,2405) ; P3.2 P3.1
  Bottom Layer w30: v2(5325,2405) v2(5325,2445) 5325,3955 P3.1
VDD_5V: C1.1 C2.2 C3.1 C4.2 C5.2 C6.2 C15.1 C16.2 C17.1 C18.2 C19.2 C20.2 P1.1 P1.2 R2.2 R3.2 R5.2 R6.2 R14.2 R15.2 R17.2 R18.2 U1.14 U2.14 U3.5 U4.5 U9.14 U10.5 U11.14 U12.5 | length 12273
  Top Layer w10: R17.2 3744.37,1005.63 3766.61,983.39 U11.14 3881.61,983.39 3914.37,950.63 R18.2 3966.26,950.63 C18.2@4032.87,1017.24 ; R2.2 3759.37,3205.63 3766.61,3198.39 U1.14 3916.61,3198.39 3944.37,3170.63 R3.2 4056.61,3252.24 C1.1 ; R5.2 3764.37,4260.63 3786.61,4238.39 U2.14 3916.61,4238.39 3944.37,4210.63 R6.2 4016.26,4210.63 C4.2 4087.87,4282.24 C3.1 ; R14.2 3804.37,2195.63 3826.61,2173.39 U9.14 3926.61,2173.39 3949.37,2150.63 R15.2 4016.26,2150.63 4067.87,2202.24 C15.1 ; C18.2 4132.87,1034.37 C17.1
  Top Layer w30: P1.2 P1.1 3000,4215 3195,4410 ; v2(3250,2310) 3250,2075 3287.4,2037.6 U10.5 3365.63,2014.17 C19.2 ; C20.2 3292.2,776.57 U12.5 3177.4,857.6 3160,875 3160,1135 3215,1190 v2(3610,1190) ; U3.5 3302.4,3102.6 3335.63,3069.37 C5.2 3335.63,3009.37 3390,2955 v2(3445,2955) ; C6.2@3314.41,4091.22 U4.5 3227.4,4162.6 3195,4195 3195,4410 ; v2(3525,4510) 3295,4510 3195,4410 ; R17.2 3830,1110 3835,1115 v2(3835,1135) ; R14.2 3805,2305.63 v2(3805,2390) ; v2(3975,3085) R3.2 ; C17.1 4242.24,1017.24 v2(4260,1035) ; v2(4180,4410) C3.1 4432.76,4282.24 4675,4040 4675,3615 4312.24,3252.24 ; C1.1 4312.24,3252.24 ; v2(4280,3145) 4280,3220 4312.24,3252.24
  Bottom Layer w30: v2(3250,2310) 3385,2445 3765,2445 3805,2405 v2(3805,2390) 3875,2460 4205,2460 4280,2535 ; v2(3445,2955) 3865,2955 3975,3065 v2(3975,3085) ; v2(3525,4510) 4105,4510 4180,4435 v2(4180,4410) ; v2(3610,1190) 3785,1190 v2@3835,1140 ; v2(4260,1035) 4280,1055 4280,2535 ; v2(4280,3145) 4280,2535
pads on no net: J1.9 J1.10 J2.9 J2.10 U1.5 U1.6 U1.7 U1.9 U1.10 U1.11 U1.12 U1.15 U2.5 U2.6 U2.7 U2.9 U2.10 U2.11 U2.12 U2.15 U5.1 U5.2 U5.4 U5.5 U6.1 U6.2 U6.4 U6.5 U7.1 U7.2 U7.4 U7.5 U8.1 U8.2 U8.4 U8.5 U9.5 U9.6 U9.7 U9.9 U9.10 U9.11 U9.12 U9.15 U11.5 U11.6 U11.7 U11.9 U11.10 U11.11 U11.12 U11.15 U13.1 U13.2 U13.4 U13.5 U14.1 U14.2 U14.4 U14.5 U15.1 U15.2 U15.4 U15.5 U16.1 U16.2 U16.4 U16.5

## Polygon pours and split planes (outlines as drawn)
GND on Top Layer "Bottom Layer-No Net" (solid, remove dead copper, pour order 5): 2300,4575 5470,4575 5470,25 2300,25 2300,4575
GND on Bottom Layer "Bottom Layer-No Net" (solid, remove dead copper, pour order 7): 2299.47,4576.37 5469.47,4576.37 5469.47,26.37 2299.47,26.37 2299.47,4576.37

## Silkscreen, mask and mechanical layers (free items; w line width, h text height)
Top Overlay:
  text "GND" at 2650,4085 h60
  text "5V" at 2875,4085 h60
  text "GND" at 5030,4045 h60
  text "3V" at 5250,4040 h60
Mechanical 13:
  the board outline again, w10

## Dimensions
2300,25 to 2300,4575 on Top Overlay
2300,4575 to 5470,4575 on Top Overlay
